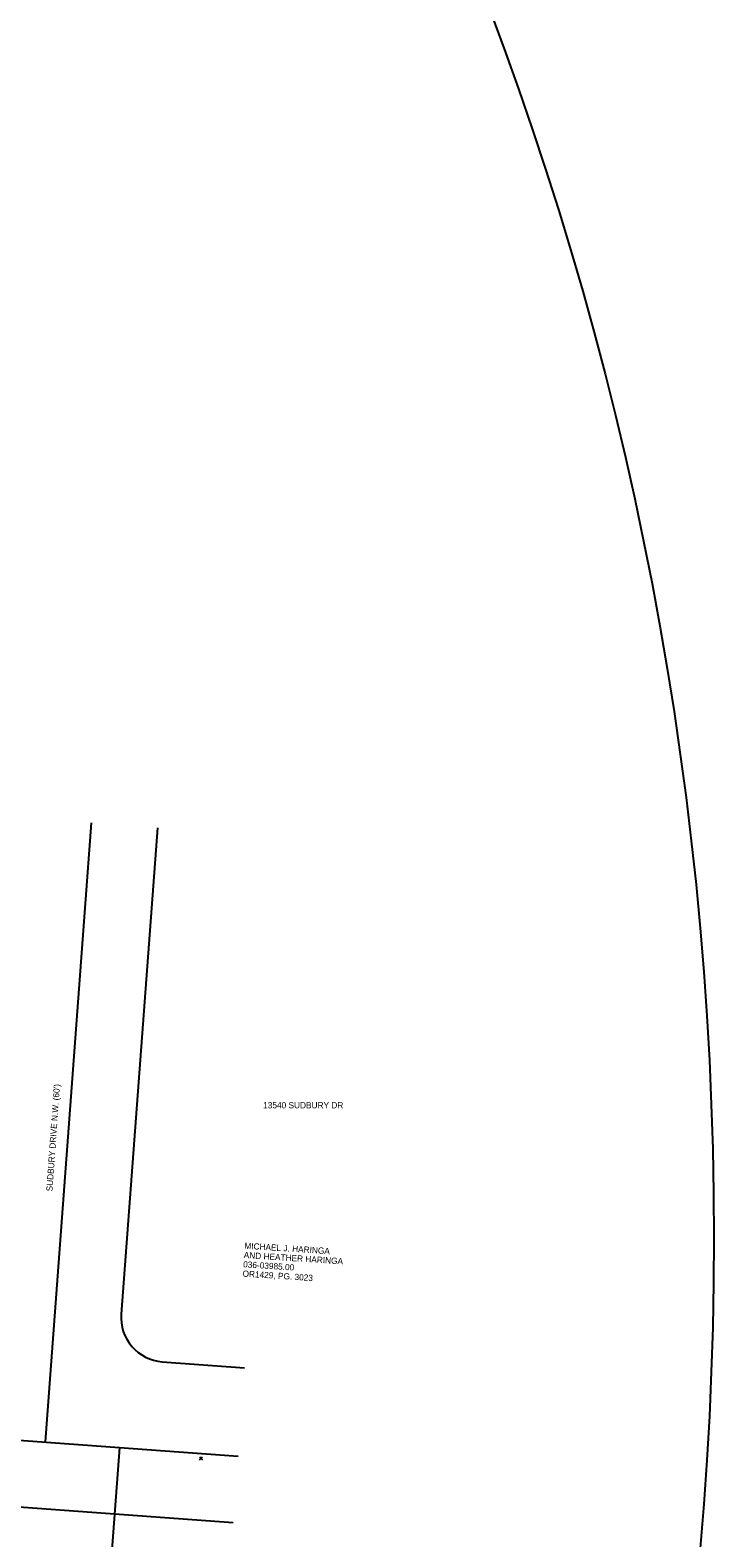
# Model space of a CAD drawing. Extents: x 1898254 to 1901377, y 701554 to 704886.
# Drawn here: x 1901068 to 1901377, y 703095 to 703775 of the extents above; entities that cross this region are included whole.
import ezdxf

# ---------------------------------------------------------------- set-up
doc = ezdxf.new("R2010")
doc.units = 0
for name, color, linetype in [('DV_X_Property_Line', 7, 'Continuous'), ('DV_X_Text', 7, 'Continuous'), ('RW_X_CL', 7, 'Continuous'), ('RW_X_Esmt_SH', 7, 'Continuous'), ('RW_X_Fee_RW', 7, 'Continuous'), ('RW_X_Text', 7, 'Continuous'), ('SC_Scratch2', 7, 'Continuous'), ('SC_Scratch5', 7, 'Continuous'), ('SV_X_Random_Point', 7, 'Continuous')]:
    doc.layers.add(name, color=color, linetype=linetype)

msp = doc.modelspace()

# ---------------------------------------------------------------- linework, layer by layer
at = {"layer": 'DV_X_Property_Line'}
msp.add_line((1901070.53, 702612.79), (1901108.73, 703135.32), dxfattribs=at)
at = {"layer": 'RW_X_CL'}
for p, q in [((1901095.87, 703417.31), (1901075, 703137.79)), ((1899815.76, 703229.84), (1901162.17, 703131.42))]:
    msp.add_line(p, q, dxfattribs=at)
at = {"layer": 'RW_X_Esmt_SH'}
msp.add_line((1900608.03, 703141.85), (1901159.98, 703101.5), dxfattribs=at)
at = {"layer": 'RW_X_Fee_RW'}
for p, q in [((1901125.79, 703415.08), (1901109.39, 703195.47)), ((1901127.88, 703174.03), (1901165.09, 703171.31))]:
    msp.add_line(p, q, dxfattribs=at)
msp.add_arc((1901129.33, 703193.98), 20, 175.7289, 265.81918, dxfattribs=at)
at = {"layer": 'SC_Scratch2'}
msp.add_circle((1899815.76, 703229.84), 1561.35, dxfattribs=at)
at = {"layer": 'SC_Scratch5'}
for p, q in [((1901125.79, 703415.08), (1901109.39, 703195.47)), ((1901127.88, 703174.03), (1901165.09, 703171.31)), ((1900608.03, 703141.85), (1901159.98, 703101.5))]:
    msp.add_line(p, q, dxfattribs=at)
msp.add_arc((1901129.33, 703193.98), 20, 175.7289, 265.81918, dxfattribs=at)
at = {"layer": 'SV_X_Random_Point'}
for p, q in [((1901144.71, 703129.76), (1901146.04, 703131.1)), ((1901144.71, 703131.1), (1901146.04, 703129.76))]:
    msp.add_line(p, q, dxfattribs=at)

# ---------------------------------------------------------------- texts
at = {"layer": 'DV_X_Text'}
msp.add_text('13540 SUDBURY DR', height=2.8, dxfattribs=at).set_placement((1901173.52, 703288.42))
for s, p in [('MICHAEL J. HARINGA', (1901164.94, 703225.03)), ('AND HEATHER HARINGA ', (1901164.67, 703220.84)), ('OR1429, PG. 3023', (1901164.13, 703212.46)), ('036-03985.00', (1901164.4, 703216.65))]:
    msp.add_text(s, height=2.8, rotation=356.3351, dxfattribs=at).set_placement(p)
at = {"layer": 'RW_X_Text'}
msp.add_text("SUDBURY DRIVE N.W. (60')", height=2.8, rotation=85.93252, dxfattribs=at).set_placement((1901078.31, 703250.84))

doc.saveas('drawing.dxf')
